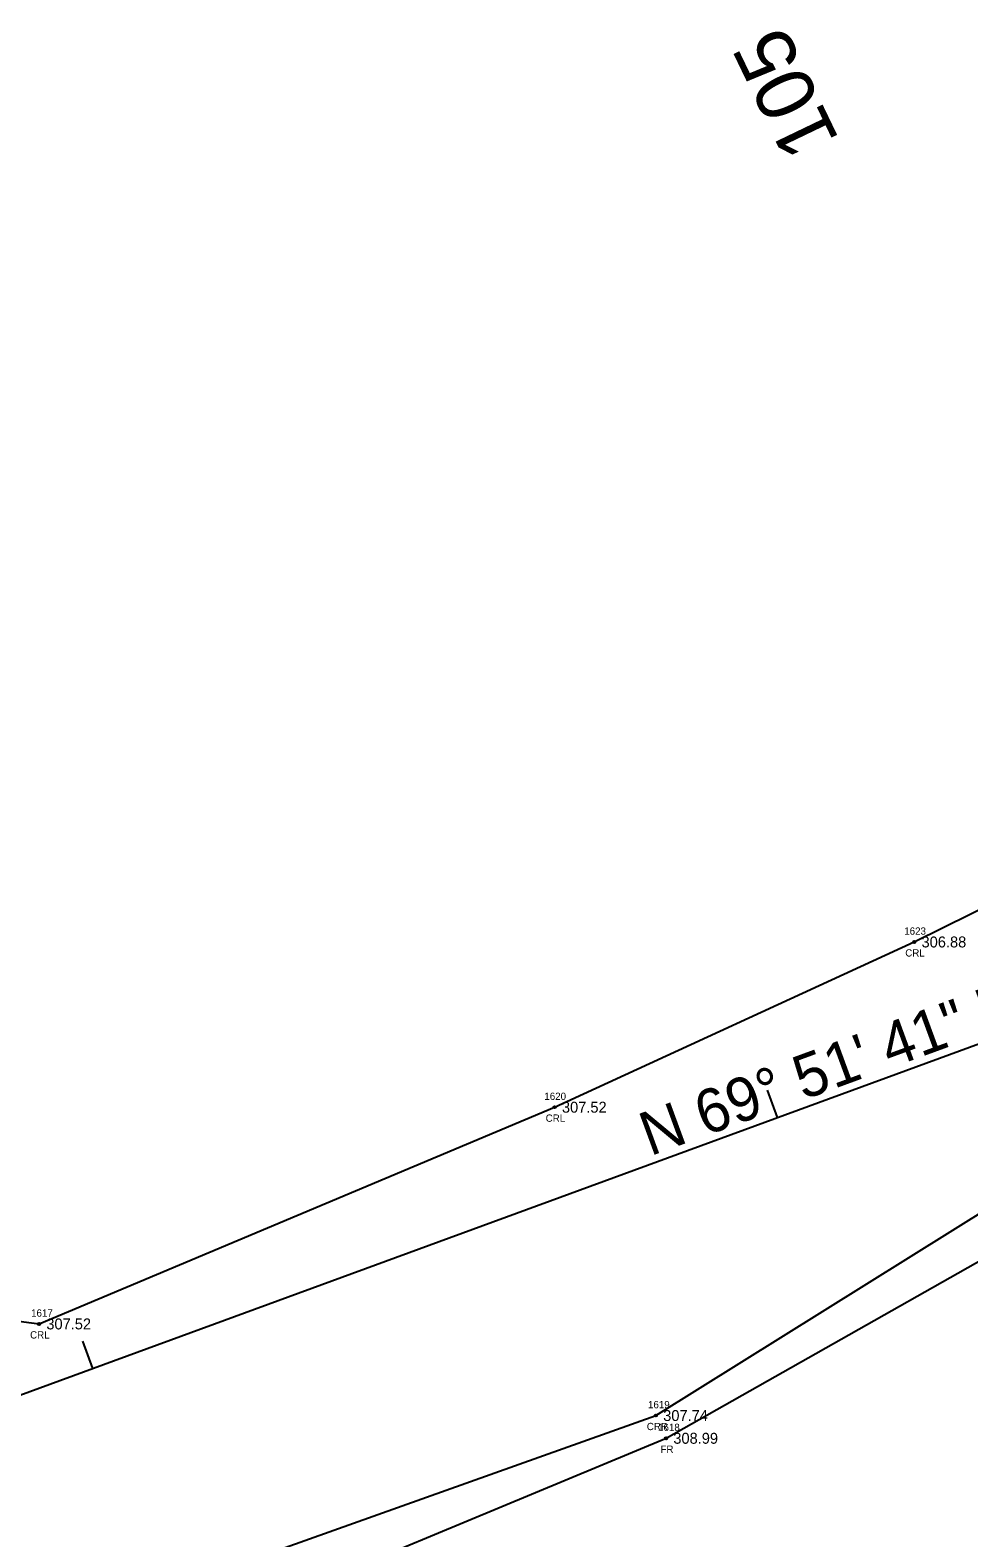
# Model space of a CAD drawing. Extents: x 1865045 to 1867370, y 910391 to 914218.
# Drawn here: x 1866113 to 1866241.8, y 910971.7 to 911178.6 of the extents above; entities that cross this region are included whole.
import ezdxf

# ---------------------------------------------------------------- set-up
doc = ezdxf.new("R2010")
doc.units = 0
for name, color, linetype in [('RD_EX_Fence_Other', 7, 'Continuous'), ('RD_EX_Fence_Other_txCode', 7, 'Continuous'), ('RD_EX_H2O', 7, 'Continuous'), ('RD_EX_H2O_txCode', 7, 'Continuous'), ('RD_EX_TX_Fence_Other_ELEV', 7, 'Continuous'), ('RD_EX_TX_H2O_ELEV', 7, 'Continuous'), ('RD_HC_Cl', 7, 'Continuous'), ('RD_HC_Data', 7, 'Continuous'), ('RD_HC_Data_Tic', 7, 'Continuous'), ('RD_HC_TX_Sta50', 7, 'Continuous'), ('RD_SMD_Locator', 7, 'Continuous')]:
    doc.layers.add(name, color=color, linetype=linetype)

msp = doc.modelspace()

# ---------------------------------------------------------------- linework, layer by layer
at = {"layer": 'RD_EX_Fence_Other'}
msp.add_lwpolyline([(1865878.66, 910821.99), (1865958.17, 910874.52), (1866026.09, 910916.1), (1866080.13, 910930.26), (1866132.1, 910957.01), (1866200.24, 910985.36), (1866266.72, 911022.99), (1866298.72, 911056.62)], dxfattribs=at)
at = {"layer": 'RD_EX_H2O'}
for points in [[(1865881.51, 910820.06), (1865958.27, 910871.4), (1866021.41, 910928.56), (1866077.02, 910947.47), (1866128.62, 910963.47), (1866198.85, 910988.48), (1866262.44, 911028.2), (1866342.24, 911081.3), (1866369.75, 911075.31), (1866430.98, 911110.24)], [(1865861.04, 910849.84), (1865929.7, 910901.29), (1866000.34, 910964.46), (1866054.46, 911008.9), (1866114.23, 911001.05), (1866184.96, 911030.79), (1866234.29, 911053.46), (1866316.28, 911094)]]:
    msp.add_lwpolyline(points, dxfattribs=at)
at = {"layer": 'RD_HC_Cl'}
msp.add_line((1866069.86, 910975.96), (1866379.46, 911089.5), dxfattribs=at)
at = {"layer": 'RD_HC_Data_Tic'}
for p, q in [((1866215.51, 911029.37), (1866214.14, 911033.13)), ((1866121.63, 910994.94), (1866120.25, 910998.7))]:
    msp.add_line(p, q, dxfattribs=at)
at = {"layer": 'RD_SMD_Locator'}
for centre in [(1866234.29, 911053.46), (1866184.96, 911030.79), (1866114.23, 911001.05), (1866198.85, 910988.48), (1866200.24, 910985.36)]:
    msp.add_circle(centre, 0.15, dxfattribs=at)

# ---------------------------------------------------------------- texts
at = {"layer": 'RD_EX_Fence_Other_txCode'}
for s, p in [('1618', (1866199.15, 910986.36)), ('FR', (1866199.48, 910983.36))]:
    msp.add_text(s, height=1, dxfattribs=at).set_placement(p)
at = {"layer": 'RD_EX_H2O_txCode'}
for s, p in [('1623', (1866232.92, 911054.46)), ('CRL', (1866233.06, 911051.46)), ('1620', (1866183.55, 911031.79)), ('CRL', (1866183.73, 911028.79)), ('1617', (1866113.14, 911002.05)), ('CRL', (1866113, 910999.05)), ('1619', (1866197.77, 910989.48)), ('CRR', (1866197.6, 910986.48))]:
    msp.add_text(s, height=1, dxfattribs=at).set_placement(p)
at = {"layer": 'RD_EX_TX_Fence_Other_ELEV'}
msp.add_text('308.99', height=1.5, dxfattribs=at).set_placement((1866201.24, 910984.61))
at = {"layer": 'RD_EX_TX_H2O_ELEV'}
for s, p in [('306.88', (1866235.29, 911052.71)), ('307.52', (1866185.96, 911030.04)), ('307.52', (1866115.23, 911000.3)), ('307.74', (1866199.85, 910987.73))]:
    msp.add_text(s, height=1.5, dxfattribs=at).set_placement(p)
at = {"layer": 'RD_HC_Data'}
msp.add_text('N 69%%d 51\' 41" E', height=6, rotation=20.1386, dxfattribs=at).set_placement((1866198.05, 911024.04))
at = {"layer": 'RD_HC_TX_Sta50'}
msp.add_text('105', height=8, rotation=115.674, dxfattribs=at).set_placement((1866224.07, 911163.47))

doc.saveas('drawing.dxf')
